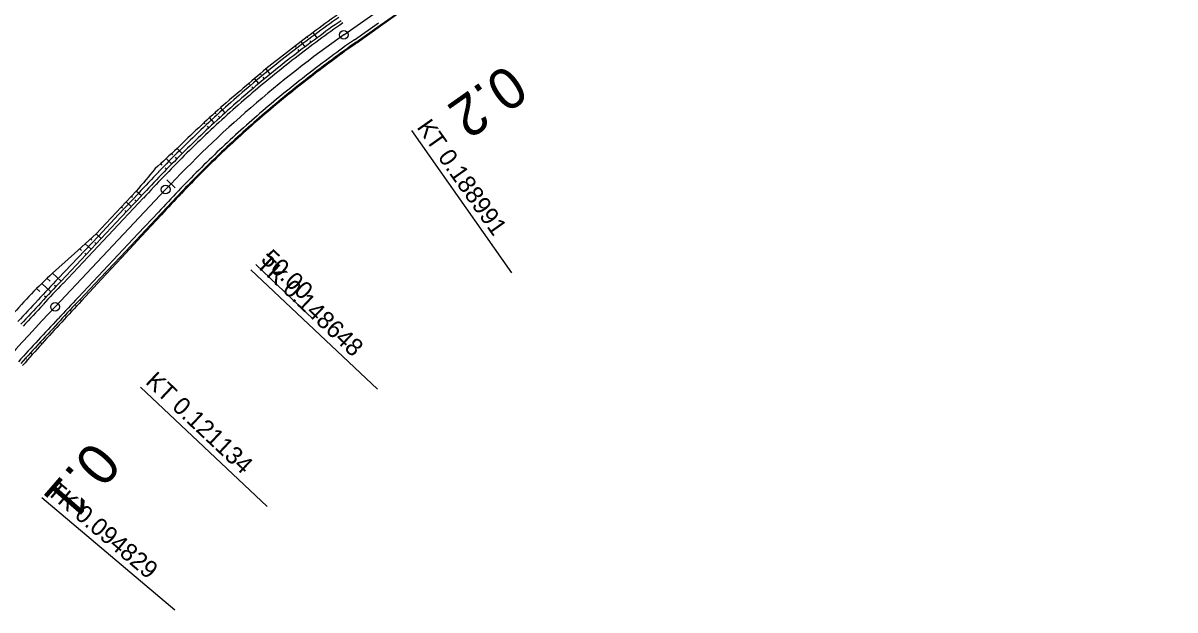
# Model space of a CAD drawing. Extents: x -481656 to -478728, y -1113199 to -1110710.
# Drawn here: x -480517.7 to -480321.2, y -1112921 to -1112820.8 of the extents above; entities that cross this region are included whole.
import ezdxf

# ---------------------------------------------------------------- set-up
doc = ezdxf.new("R2010")
doc.units = 0
for name, color, linetype in [('C14_HATCH_SLOPE_L', 7, 'Continuous'), ('C14_HATCH_SLOPE_R', 7, 'Continuous'), ('C14_HECTOMETRY', 7, 'Continuous'), ('C14_HLBODY', 7, 'Continuous'), ('C14_HRANA_TELESO', 7, 'Continuous'), ('C14_KORUNA', 7, 'Continuous'), ('C14_OSA', 7, 'Continuous'), ('C14_PRIKOP', 7, 'Continuous'), ('C14_STANICENI', 7, 'Continuous'), ('C14_VOZOVKA', 7, 'Continuous'), ('C14_ZPEVKRAJ', 7, 'Continuous')]:
    doc.layers.add(name, color=color, linetype=linetype)

msp = doc.modelspace()

# ---------------------------------------------------------------- linework, layer by layer
at = {"layer": 'C14_HATCH_SLOPE_L'}
for p, q in [((-480469.08, -1112823.41), (-480469.22, -1112823.23)), ((-480467.53, -1112823.38), (-480468.2, -1112822.46)), ((-480471.1, -1112824.95), (-480471.23, -1112824.78)), ((-480470.56, -1112825.65), (-480470.76, -1112825.39)), ((-480469.55, -1112824.89), (-480470.23, -1112824)), ((-480468.54, -1112824.13), (-480468.74, -1112823.86)), ((-480477.07, -1112829.68), (-480477.22, -1112829.5)), ((-480475.52, -1112829.57), (-480476.24, -1112828.68)), ((-480479.01, -1112831.32), (-480479.15, -1112831.15)), ((-480477.47, -1112831.18), (-480478.19, -1112830.32)), ((-480476.5, -1112830.37), (-480476.71, -1112830.11)), ((-480478.44, -1112831.99), (-480478.65, -1112831.74)), ((-480483.2, -1112836.15), (-480483.98, -1112835.29)), ((-480485.07, -1112837.86), (-480485.86, -1112836.99)), ((-480484.75, -1112836.32), (-480484.92, -1112836.14)), ((-480484.13, -1112837), (-480484.36, -1112836.76)), ((-480486.62, -1112838.04), (-480486.8, -1112837.85)), ((-480485.99, -1112838.72), (-480486.22, -1112838.47)), ((-480492.12, -1112843.32), (-480492.33, -1112843.11)), ((-480490.54, -1112843.11), (-480491.39, -1112842.26)), ((-480493.94, -1112845.09), (-480494.21, -1112844.83)), ((-480492.32, -1112844.91), (-480493.28, -1112843.97)), ((-480491.43, -1112844), (-480491.66, -1112843.77)), ((-480493.2, -1112845.81), (-480493.44, -1112845.58)), ((-480499.04, -1112850.65), (-480499.23, -1112850.47)), ((-480498.37, -1112851.28), (-480498.61, -1112851.05)), ((-480497.51, -1112850.37), (-480498.38, -1112849.56)), ((-480500.75, -1112852.47), (-480500.93, -1112852.3)), ((-480500.08, -1112853.1), (-480500.33, -1112852.87)), ((-480499.23, -1112852.19), (-480500.08, -1112851.39)), ((-480504.37, -1112857.65), (-480505.24, -1112856.83)), ((-480506.08, -1112859.47), (-480507.09, -1112858.52)), ((-480505.94, -1112857.89), (-480506.16, -1112857.68)), ((-480505.22, -1112858.56), (-480505.47, -1112858.33)), ((-480507.72, -1112859.65), (-480508.02, -1112859.37)), ((-480506.94, -1112860.38), (-480507.18, -1112860.15)), ((-480513.07, -1112864.91), (-480513.58, -1112864.43)), ((-480511.22, -1112864.93), (-480512.69, -1112863.55)), ((-480514.83, -1112866.69), (-480515.38, -1112866.17)), ((-480512.93, -1112866.75), (-480514.48, -1112865.3)), ((-480512.08, -1112865.84), (-480512.32, -1112865.62)), ((-480513.79, -1112867.66), (-480514.03, -1112867.44))]:
    msp.add_line(p, q, dxfattribs=at)
at = {"layer": 'C14_HATCH_SLOPE_R'}
for p, q in [((-480456.75, -1112821.24), (-480456.68, -1112821.34)), ((-480459.81, -1112823.4), (-480459.77, -1112823.46)), ((-480459.73, -1112823.52), (-480459.73, -1112823.52)), ((-480458.79, -1112822.68), (-480458.71, -1112822.79)), ((-480457.77, -1112821.96), (-480457.73, -1112822.01)), ((-480457.7, -1112822.06), (-480457.7, -1112822.06)), ((-480464.86, -1112827.01), (-480464.75, -1112827.15)), ((-480467.83, -1112829.23), (-480467.78, -1112829.3)), ((-480467.72, -1112829.37), (-480467.72, -1112829.37)), ((-480466.84, -1112828.48), (-480466.74, -1112828.62)), ((-480465.85, -1112827.74), (-480465.8, -1112827.81)), ((-480465.75, -1112827.89), (-480465.75, -1112827.89)), ((-480472.68, -1112833.06), (-480472.58, -1112833.19)), ((-480475.53, -1112835.43), (-480475.48, -1112835.49)), ((-480474.59, -1112834.63), (-480474.48, -1112834.75)), ((-480473.64, -1112833.84), (-480473.58, -1112833.9)), ((-480473.53, -1112833.97), (-480473.53, -1112833.97)), ((-480475.43, -1112835.55), (-480475.43, -1112835.55)), ((-480482.01, -1112841.16), (-480481.91, -1112841.27)), ((-480481.1, -1112840.32), (-480481.05, -1112840.38)), ((-480481, -1112840.43), (-480481, -1112840.43)), ((-480480.18, -1112839.49), (-480480.09, -1112839.6)), ((-480482.91, -1112842), (-480482.86, -1112842.06)), ((-480482.81, -1112842.11), (-480482.81, -1112842.11)), ((-480488.23, -1112847.17), (-480488.17, -1112847.23)), ((-480487.36, -1112846.3), (-480487.24, -1112846.41)), ((-480489.96, -1112848.94), (-480489.9, -1112849)), ((-480489.83, -1112849.06), (-480489.83, -1112849.06)), ((-480489.1, -1112848.05), (-480488.98, -1112848.17)), ((-480488.11, -1112847.29), (-480488.11, -1112847.29)), ((-480495.09, -1112854.37), (-480495.02, -1112854.43)), ((-480494.95, -1112854.5), (-480494.95, -1112854.5)), ((-480494.24, -1112853.46), (-480494.1, -1112853.59)), ((-480496.81, -1112856.19), (-480496.73, -1112856.26)), ((-480496.66, -1112856.33), (-480496.66, -1112856.33)), ((-480495.95, -1112855.28), (-480495.8, -1112855.41)), ((-480501.09, -1112860.74), (-480500.92, -1112860.9)), ((-480502.8, -1112862.56), (-480502.62, -1112862.73)), ((-480501.95, -1112861.65), (-480501.86, -1112861.73)), ((-480501.77, -1112861.82), (-480501.77, -1112861.82)), ((-480503.66, -1112863.47), (-480503.56, -1112863.56)), ((-480503.47, -1112863.65), (-480503.47, -1112863.65)), ((-480507.94, -1112868.02), (-480507.71, -1112868.24)), ((-480510.52, -1112870.75), (-480510.39, -1112870.87)), ((-480509.66, -1112869.84), (-480509.41, -1112870.07)), ((-480508.8, -1112868.93), (-480508.68, -1112869.04)), ((-480508.56, -1112869.16), (-480508.56, -1112869.16)), ((-480510.26, -1112870.99), (-480510.26, -1112870.99)), ((-480515.59, -1112876.22), (-480515.44, -1112876.36)), ((-480515.29, -1112876.5), (-480515.29, -1112876.5)), ((-480514.75, -1112875.3), (-480514.46, -1112875.58)), ((-480517.27, -1112878.06), (-480517.11, -1112878.21)), ((-480516.95, -1112878.36), (-480516.95, -1112878.36)), ((-480516.43, -1112877.14), (-480516.12, -1112877.43))]:
    msp.add_line(p, q, dxfattribs=at)
at = {"layer": 'C14_HLBODY'}
for p, q in [((-480451.43, -1112839.21), (-480434.33, -1112863.49)), ((-480478.81, -1112862.97), (-480457.19, -1112883.32)), ((-480497.67, -1112883), (-480476.04, -1112903.36)), ((-480514.49, -1112901.83), (-480491.82, -1112921.03))]:
    msp.add_line(p, q, dxfattribs=at)
for centre in [(-480462.96, -1112822.86), (-480493.37, -1112849.26), (-480512.23, -1112869.29)]:
    msp.add_circle(centre, 0.75, dxfattribs=at)
at = {"layer": 'C14_HRANA_TELESO'}
for p, q in [((-480456.68, -1112821.34), (-480452.61, -1112818.43)), ((-480460.75, -1112824.24), (-480456.68, -1112821.34)), ((-480501.79, -1112853.21), (-480498.38, -1112849.56)), ((-480505.24, -1112856.83), (-480501.79, -1112853.21)), ((-480497.51, -1112857.24), (-480494.1, -1112853.59)), ((-480508.94, -1112860.21), (-480505.24, -1112856.83)), ((-480500.92, -1112860.9), (-480497.51, -1112857.24)), ((-480512.69, -1112863.55), (-480508.94, -1112860.21)), ((-480504.32, -1112864.57), (-480500.92, -1112860.9)), ((-480507.71, -1112868.24), (-480504.32, -1112864.57))]:
    msp.add_line(p, q, dxfattribs=at)
for centre, radius, start, end in [((-480406.48, -1112903.28), 101.69, 124.5115, 127.367), ((-480346.31, -1112985.25), 203.37, 126.8231, 128.2556), ((-480349.3, -1112987.56), 203.37, 127.1932, 128.6257), ((-480404.73, -1112905.61), 98.78, 124.5477, 127.42), ((-480348.06, -1112986.58), 197.57, 126.2011, 127.6335), ((-480346.09, -1112984.94), 203.37, 129.7928, 131.2253), ((-480348.01, -1112986.56), 197.58, 127.6494, 129.0818), ((-480350.02, -1112988.32), 203.38, 129.7653, 131.1978), ((-480347.98, -1112986.54), 197.59, 129.0916, 130.524), ((-480348.62, -1112987.15), 203.43, 131.7096, 133.1421), ((-480347.99, -1112986.56), 197.6, 130.5197, 131.9521), ((-480348.03, -1112986.62), 203.45, 133.3653, 134.7977), ((-480347.78, -1112986.38), 197.6, 132.0319, 133.4642), ((-480355.78, -1112994.12), 203.59, 131.7635, 133.1981), ((-480347.31, -1112985.92), 197.6, 133.6544, 135.0868), ((-480028.2, -1113240.06), 611.2, 139.81695, 140.28883), ((-480347.32, -1112985.91), 197.58, 135.0878, 136.5202), ((-480059.94, -1113257.1), 592.72, 136.6137, 137.09544), ((-480338.31, -1113045.81), 252.24, 133.7342, 134.8733), ((-480143.94, -1113207.39), 504.45, 137.5711, 138.1441), ((-480326.88, -1113038.97), 248.69, 136.646, 137.7966), ((-480145.35, -1113208.95), 497.37, 137.3384, 137.9114), ((-480145.33, -1113208.87), 497.33, 137.9203, 138.4933)]:
    msp.add_arc(centre, radius, start, end, dxfattribs=at)
at = {"layer": 'C14_KORUNA'}
for p, q in [((-480456.75, -1112821.24), (-480452.66, -1112818.36)), ((-480460.83, -1112824.12), (-480456.75, -1112821.24)), ((-480500.94, -1112854.01), (-480497.51, -1112850.37)), ((-480504.37, -1112857.65), (-480500.94, -1112854.01)), ((-480497.66, -1112857.1), (-480494.24, -1112853.46)), ((-480507.79, -1112861.29), (-480504.37, -1112857.65)), ((-480501.09, -1112860.74), (-480497.66, -1112857.1)), ((-480504.52, -1112864.38), (-480501.09, -1112860.74)), ((-480511.22, -1112864.93), (-480507.79, -1112861.29)), ((-480507.94, -1112868.02), (-480504.52, -1112864.38))]:
    msp.add_line(p, q, dxfattribs=at)
for centre, radius, start, end in [((-480406.59, -1112904.08), 101.12, 124.2002, 127.0588), ((-480347.75, -1112986.35), 202.25, 126.3155, 127.7479), ((-480405.27, -1112905.9), 98.88, 124.1916, 127.0632), ((-480347.75, -1112986.35), 202.25, 127.7479, 129.1803), ((-480347.75, -1112986.35), 197.75, 126.3155, 127.7479), ((-480347.75, -1112986.35), 202.25, 129.1803, 130.6127), ((-480347.75, -1112986.35), 197.75, 127.7479, 129.1803), ((-480347.75, -1112986.35), 202.25, 130.6127, 132.0451), ((-480347.75, -1112986.35), 197.75, 129.1803, 130.6127), ((-480347.75, -1112986.35), 202.25, 132.0451, 133.4775), ((-480347.75, -1112986.35), 197.75, 130.6127, 132.0451), ((-480347.75, -1112986.35), 202.25, 133.4775, 134.9099), ((-480347.75, -1112986.35), 197.75, 132.0451, 133.4775), ((-480347.75, -1112986.35), 202.25, 134.9099, 136.3423), ((-480347.75, -1112986.35), 197.75, 133.4775, 134.9099), ((-480054.39, -1113264.84), 606.75, 136.44006, 136.91365), ((-480347.75, -1112986.35), 197.75, 134.9099, 136.3423), ((-480060.94, -1113258.67), 593.25, 136.437, 136.91843), ((-480330.05, -1113038.83), 251.12, 136.1734, 137.3154), ((-480148.17, -1113212.01), 502.25, 136.8596, 137.4326), ((-480328.41, -1113040.37), 248.88, 136.1694, 137.3193), ((-480148.17, -1113212.01), 497.75, 136.8596, 137.4326), ((-480148.17, -1113212.01), 497.75, 137.4326, 138.0055)]:
    msp.add_arc(centre, radius, start, end, dxfattribs=at)
at = {"layer": 'C14_OSA'}
for p, q in [((-480462.96, -1112822.86), (-480319.49, -1112721.76)), ((-480512.23, -1112869.29), (-480493.37, -1112849.26))]:
    msp.add_line(p, q, dxfattribs=at)
for centre, radius, start, end in [((-480347.75, -1112986.35), 200, 125.1722, 136.7297), ((-480148.17, -1113212.01), 500, 136.7297, 139.744)]:
    msp.add_arc(centre, radius, start, end, dxfattribs=at)
at = {"layer": 'C14_PRIKOP'}
for p, q in [((-480501.42, -1112853.55), (-480498, -1112849.92)), ((-480504.85, -1112857.2), (-480501.42, -1112853.55)), ((-480508.28, -1112860.84), (-480504.85, -1112857.2)), ((-480511.71, -1112864.48), (-480508.28, -1112860.84))]:
    msp.add_line(p, q, dxfattribs=at)
for centre, radius, start, end in [((-480406.78, -1112903.81), 101.46, 124.2014, 127.0582), ((-480347.75, -1112986.35), 202.92, 126.3155, 127.7479), ((-480347.75, -1112986.35), 202.92, 127.7479, 129.1803), ((-480347.75, -1112986.35), 202.92, 129.1803, 130.6127), ((-480347.75, -1112986.35), 202.92, 130.6127, 132.0451), ((-480347.75, -1112986.35), 202.92, 132.0451, 133.4775), ((-480347.75, -1112986.35), 202.92, 133.4775, 134.9099), ((-480347.75, -1112986.35), 202.92, 134.9099, 136.3423), ((-480053.42, -1113265.76), 608.75, 136.4405, 136.91296), ((-480330.29, -1113038.6), 251.46, 136.174, 137.3148), ((-480148.17, -1113212.01), 502.92, 136.8596, 137.4326)]:
    msp.add_arc(centre, radius, start, end, dxfattribs=at)
at = {"layer": 'C14_STANICENI'}
for p, q in [((-480491.72, -1112848.97), (-480493.17, -1112847.59)), ((-480477.97, -1112862.08), (-480468.21, -1112871.4))]:
    msp.add_line(p, q, dxfattribs=at)
at = {"layer": 'C14_VOZOVKA'}
for p, q in [((-480461.12, -1112823.71), (-480457.04, -1112820.83)), ((-480500.58, -1112854.35), (-480497.15, -1112850.71)), ((-480498.03, -1112856.75), (-480494.6, -1112853.11)), ((-480504, -1112858), (-480500.58, -1112854.35)), ((-480501.45, -1112860.39), (-480498.03, -1112856.75)), ((-480507.43, -1112861.64), (-480504, -1112858)), ((-480504.88, -1112864.03), (-480501.45, -1112860.39)), ((-480510.86, -1112865.28), (-480507.43, -1112861.64)), ((-480508.31, -1112867.68), (-480504.88, -1112864.03))]:
    msp.add_line(p, q, dxfattribs=at)
for centre, radius, start, end in [((-480406.44, -1112904.28), 100.88, 124.1993, 127.0593), ((-480347.75, -1112986.35), 201.75, 126.3155, 127.7479), ((-480405.42, -1112905.7), 99.13, 124.1926, 127.0627), ((-480347.75, -1112986.35), 201.75, 127.7479, 129.1803), ((-480347.75, -1112986.35), 198.25, 126.3155, 127.7479), ((-480347.75, -1112986.35), 201.75, 129.1803, 130.6127), ((-480347.75, -1112986.35), 198.25, 127.7479, 129.1803), ((-480347.75, -1112986.35), 201.75, 130.6127, 132.0451), ((-480347.75, -1112986.35), 198.25, 129.1803, 130.6127), ((-480347.75, -1112986.35), 201.75, 132.0451, 133.4775), ((-480347.75, -1112986.35), 198.25, 130.6127, 132.0451), ((-480347.75, -1112986.35), 198.25, 132.0451, 133.4775), ((-480347.75, -1112986.35), 201.75, 133.4775, 134.9099), ((-480347.75, -1112986.35), 198.25, 133.4775, 134.9099), ((-480347.75, -1112986.35), 201.75, 134.9099, 136.3423), ((-480055.12, -1113264.16), 605.25, 136.43973, 136.91417), ((-480347.75, -1112986.35), 198.25, 134.9099, 136.3423), ((-480060.21, -1113259.35), 594.75, 136.43735, 136.91789), ((-480329.87, -1113039), 250.88, 136.173, 137.3158), ((-480328.59, -1113040.2), 249.12, 136.1698, 137.3189), ((-480148.17, -1113212.01), 501.75, 136.8596, 137.4326), ((-480148.17, -1113212.01), 498.25, 136.8596, 137.4326), ((-480148.17, -1113212.01), 498.25, 137.4326, 138.0055)]:
    msp.add_arc(centre, radius, start, end, dxfattribs=at)
at = {"layer": 'C14_ZPEVKRAJ'}
for p, q in [((-480461.12, -1112823.71), (-480457.04, -1112820.83)), ((-480500.58, -1112854.35), (-480497.15, -1112850.71)), ((-480498.03, -1112856.75), (-480494.6, -1112853.11)), ((-480504, -1112858), (-480500.58, -1112854.35)), ((-480501.45, -1112860.39), (-480498.03, -1112856.75)), ((-480507.43, -1112861.64), (-480504, -1112858)), ((-480504.88, -1112864.03), (-480501.45, -1112860.39)), ((-480510.86, -1112865.28), (-480507.43, -1112861.64)), ((-480508.31, -1112867.68), (-480504.88, -1112864.03))]:
    msp.add_line(p, q, dxfattribs=at)
for centre, radius, start, end in [((-480406.44, -1112904.28), 100.88, 124.1993, 127.0593), ((-480347.75, -1112986.35), 201.75, 126.3155, 127.7479), ((-480405.42, -1112905.7), 99.13, 124.1926, 127.0627), ((-480347.75, -1112986.35), 201.75, 127.7479, 129.1803), ((-480347.75, -1112986.35), 198.25, 126.3155, 127.7479), ((-480347.75, -1112986.35), 201.75, 129.1803, 130.6127), ((-480347.75, -1112986.35), 198.25, 127.7479, 129.1803), ((-480347.75, -1112986.35), 201.75, 130.6127, 132.0451), ((-480347.75, -1112986.35), 198.25, 129.1803, 130.6127), ((-480347.75, -1112986.35), 201.75, 132.0451, 133.4775), ((-480347.75, -1112986.35), 198.25, 130.6127, 132.0451), ((-480347.75, -1112986.35), 198.25, 132.0451, 133.4775), ((-480347.75, -1112986.35), 201.75, 133.4775, 134.9099), ((-480347.75, -1112986.35), 198.25, 133.4775, 134.9099), ((-480347.75, -1112986.35), 201.75, 134.9099, 136.3423), ((-480055.12, -1113264.16), 605.25, 136.43973, 136.91417), ((-480347.75, -1112986.35), 198.25, 134.9099, 136.3423), ((-480060.21, -1113259.35), 594.75, 136.43735, 136.91789), ((-480329.87, -1113039), 250.88, 136.173, 137.3158), ((-480328.59, -1113040.2), 249.12, 136.1698, 137.3189), ((-480148.17, -1113212.01), 501.75, 136.8596, 137.4326), ((-480148.17, -1113212.01), 498.25, 136.8596, 137.4326), ((-480148.17, -1113212.01), 498.25, 137.4326, 138.0055)]:
    msp.add_arc(centre, radius, start, end, dxfattribs=at)

# ---------------------------------------------------------------- texts
at = {"layer": 'C14_HECTOMETRY'}
for s, height, rotation, p in [('0.2', 7, 215.1265, (-480435.04, -1112827.67)), ('0.1', 6.999, 229.1058, (-480505.91, -1112891.89))]:
    msp.add_text(s, height=height, rotation=rotation, dxfattribs=at).set_placement(p)
at = {"layer": 'C14_HLBODY'}
for s, rotation, p in [('KT 0.188991', 305.1722, (-480450.62, -1112838.63)), ('TK 0.148648', 316.7297, (-480478.13, -1112862.24)), ('KT 0.121134', 316.7297, (-480496.98, -1112882.27)), ('TK 0.094829', 319.744, (-480513.84, -1112901.07))]:
    msp.add_text(s, height=2.999, rotation=rotation, dxfattribs=at).set_placement(p)
at = {"layer": 'C14_STANICENI'}
msp.add_text('50.00', height=2.999, rotation=316.3423, dxfattribs=at).set_placement((-480477.28, -1112861.36))

doc.saveas('drawing.dxf')
